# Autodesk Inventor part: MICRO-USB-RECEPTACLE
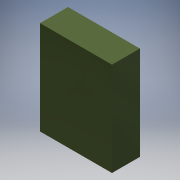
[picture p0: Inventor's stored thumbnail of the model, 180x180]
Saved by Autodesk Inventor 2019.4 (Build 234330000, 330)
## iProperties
Created: 2019-11
Part Number: MICRO-USB-RECEPTACLE
Material: Generic
Document SubType Name: Modeling
Designer: Willist
Density: 1 g/cm^3
Appearance: 47589-0002, MICRO-USB-RECEPTACLE
Author: Willist
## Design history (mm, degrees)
sketch "47589-0002, MICRO-USB-RECEPTACLE_15"
  geometry: L1 (-2.75, 4.025)-(3.425, 4.025); L2 (3.425, 4.025)-(3.425, -4.025); L3 (3.425, -4.025)-(-2.75, -4.025); L4 (-2.75, -4.025)-(-2.75, 4.025)
  constraints: 8 end point
extrude "Extrusion1" join sketch "47589-0002, MICRO-USB-RECEPTACLE_15" distance "d0" = 1; taper "d1" = 0 deg
sketch "Sketch2"
  geometry: L1 (-2.75, -4.025)-(3.425, -4.025) reference; L2 (3.425, 4.025)-(-2.75, 4.025) reference; L3 (-2.75, -4.025)-(3.425, -4.025); L4 (3.425, -4.025)-(3.425, 4.025); L5 (3.425, 4.025)-(-2.75, 4.025); L6 (-2.75, 4.025)-(-2.75, -4.025); 1 further point
  constraints: 8 end point, 2 parallel, 1 horizontal, 1 perpendicular
extrude "Extrusion2" join sketch "Sketch2" distance "d2" = 1.4; taper "d3" = 0 deg
body "Solid1"
